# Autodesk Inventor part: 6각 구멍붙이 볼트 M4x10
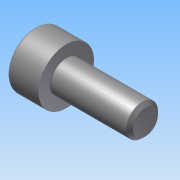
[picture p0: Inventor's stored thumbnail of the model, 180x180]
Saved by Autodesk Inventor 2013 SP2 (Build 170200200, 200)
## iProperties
Created: 2026-07
Part Number: 6각 구멍붙이 볼트 M4x10
Material: Generic
Document SubType Name: Modeling
Designer: aa
Density: 1 g/cm^3
Author: aa
변환 표준: STEP AP214IS
전처리기: Build: 200, Release: 2013 SP2 Update 6 - Date: Thu 07/17/2014
전송 단위: 밀리미터
불확실성: 0.01
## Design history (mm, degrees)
node "6각 구멍붙이 볼트 M4x101"
body "Solid1"
node "기준1"
